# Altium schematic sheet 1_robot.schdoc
size 302 x 203 mm; Symbol: Altium_A4; Device: Altium_A4; Width: 1150; Height: 760; X Region Count: 6; Y Region Count: 4; Blade Width: 20; Region Start: 1; Title Block Position: 3; @Page No: 1; @Page Count: 1; @Schematic Name: robot; @Project Name: robot; @Board Name: robot; @Update Date: 2025-04-05; @Create Time: 22:42:32; @Update Time: 23:08:08; @Page Name: robot; @Create Date: 2025-04-01
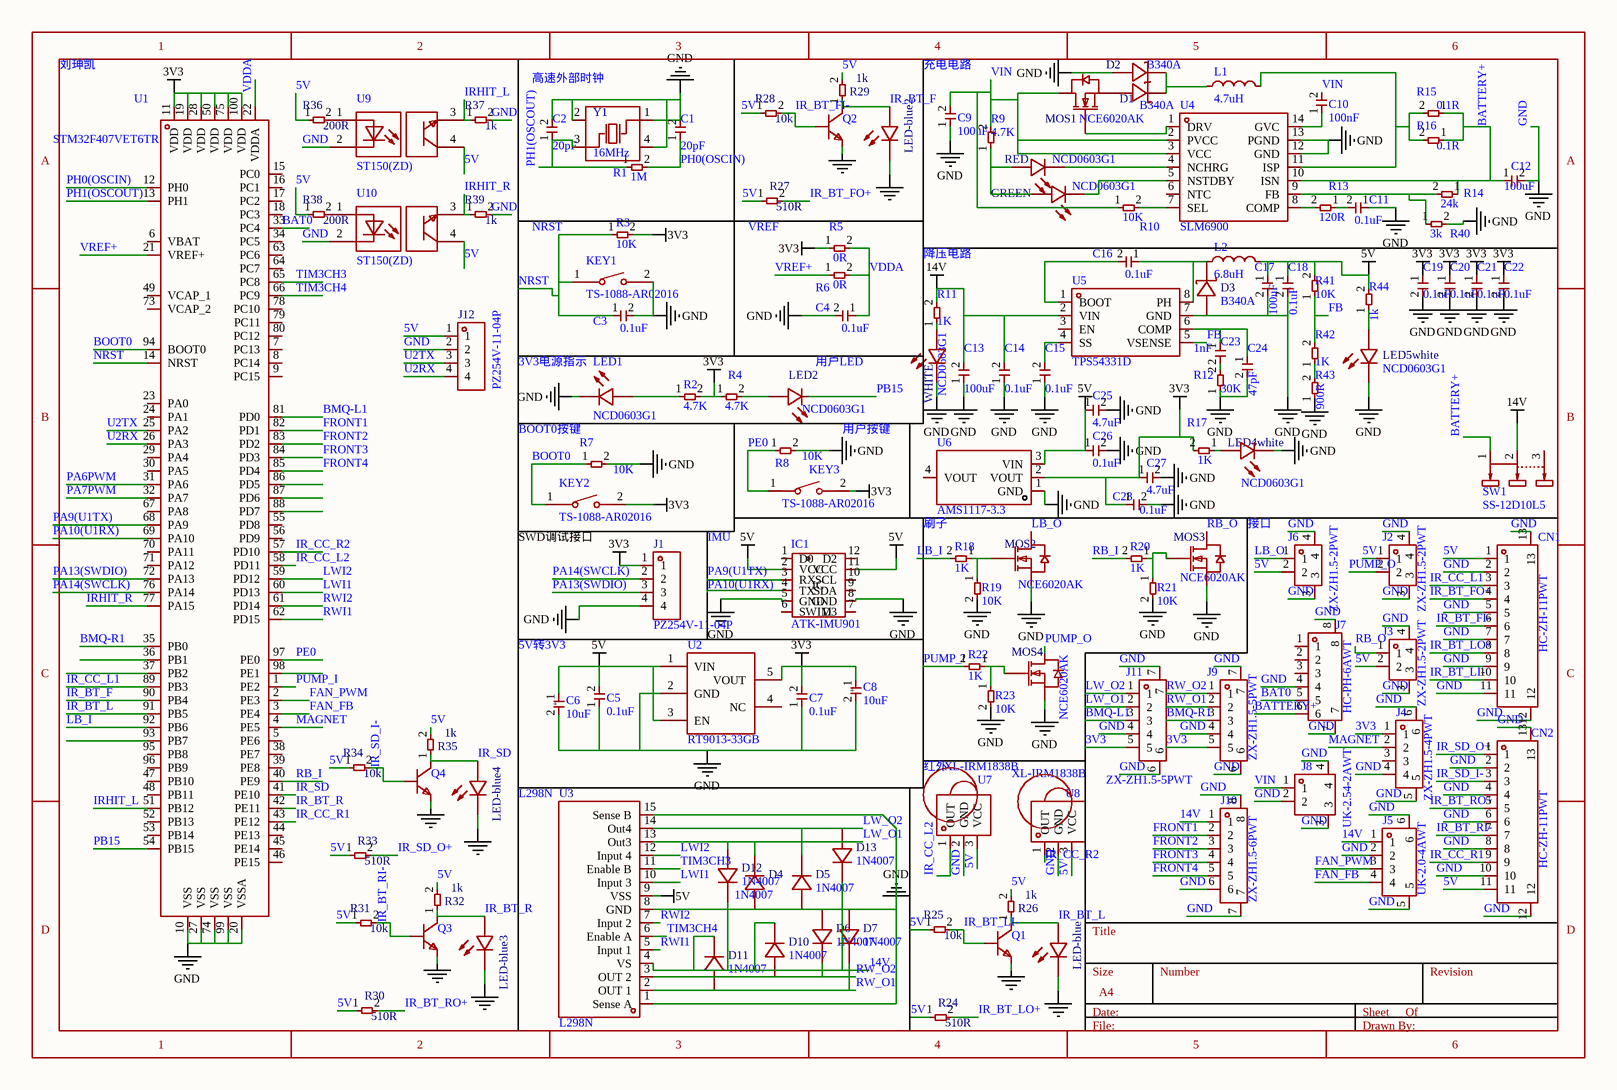
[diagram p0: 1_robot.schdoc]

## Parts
C1  20pF  [C0805]
C2  20pF  [C0805]
C3  0.1uF  [C0805]
C4  0.1uF  [C0805]
C5  0.1uF  [C0805]
C6  10uF  [c8050]
C7  0.1uF  [C0805]
C8  10uF  [c8050]
C9  100uF  [C0805]
C10  100nF  [C0805]
C11  0.1uF  [C0805]
C12  100uF  [C0805]
C13  100uF  [C0805]
C14  0.1uF  [C0805]
C15  0.1uF  [C0805]
C16  0.1uF  [C0805]
C17  100uF  [C0805]
C18  0.1uF  [C0805]
C19  0.1uF  [C0805]
C20  0.1uF  [C0805]
C21  0.1uF  [C0805]
C22  0.1uF  [C0805]
C23  1nF  [C0805]
C24  47pF  [C0805]
C25  4.7uF  [C0805]
C26  0.1uF  [C0805]
C27  4.7uF  [C0805]
C28  0.1uF  [C0805]
CN1  HC-ZH-11PWT  [CONN-SMD_11P-P1.50_HCTL_HC-ZH-11PWT]
CN2  HC-ZH-11PWT  [CONN-SMD_11P-P1.50_HCTL_HC-ZH-11PWT]
D1  B340A  [SMA_L4.3-W2.6-LS5.1-RD]
D2  B340A  [SMA_L4.3-W2.6-LS5.1-RD]
D3  B340A  [SMA_L4.3-W2.6-LS5.1-RD]
D4  1N4007  [SMA_L4.3-W2.5-LS5.0-RD]
D5  1N4007  [SMA_L4.3-W2.5-LS5.0-RD]
D6  1N4007  [SMA_L4.3-W2.5-LS5.0-RD]
D7  1N4007  [SMA_L4.3-W2.5-LS5.0-RD]
D10  1N4007  [SMA_L4.3-W2.5-LS5.0-RD]
D11  1N4007  [SMA_L4.3-W2.5-LS5.0-RD]
D12  1N4007  [SMA_L4.3-W2.5-LS5.0-RD]
D13  1N4007  [SMA_L4.3-W2.5-LS5.0-RD]
GREEN  NCD0603G1  [LED0603-RD_1]
IC1  ATK-IMU901  [COMM-SMD_12P-L16.0-W15.5-P2.54_ATK-IMU901]
J1  PZ254V-11-04P  [HDR-TH_4P-P2.54-V-M]
J2  ZX-ZH1.5-2PWT  [CONN-SMD_2P-P1.50_ZX-ZH1.5-2PWT]
J3  ZX-ZH1.5-2PWT  [CONN-SMD_2P-P1.50_ZX-ZH1.5-2PWT]
J4  ZX-ZH1.5-4PWT  [CONN-SMD_4P-P1.50_ZX-ZH1.5-4PWT]
J5  UK-2.0-4AWT  [CONN-SMD_4P-P2.00_USAKRO_UK-2.0-4AWT]
J6  ZX-ZH1.5-2PWT  [CONN-SMD_2P-P1.50_ZX-ZH1.5-2PWT]
J7  HC-PH-6AWT  [CONN-SMD_6P-P2.00_HCTL_HC-PH-6AWT]
J8  UK-2.54-2AWT  [CONN-SMD_2P-P2.54_USAKRO_UK-2.54-2AWT]
J9  ZX-ZH1.5-5PWT  [CONN-SMD_5P-P1.50_ZX-ZH1.5-5PWT]
J10  ZX-ZH1.5-6PWT  [CONN-SMD_6P-P1.50_ZX-ZH1.5-6PWT]
J11  ZX-ZH1.5-5PWT  [CONN-SMD_5P-P1.50_ZX-ZH1.5-5PWT]
J12  PZ254V-11-04P  [HDR-TH_4P-P2.54-V-M]
KEY1  TS-1088-AR02016  [SW-SMD_L3.9-W3.0-P4.45]
KEY2  TS-1088-AR02016  [SW-SMD_L3.9-W3.0-P4.45]
KEY3  TS-1088-AR02016  [SW-SMD_L3.9-W3.0-P4.45]
L1  4.7uH  [IND-SMD_L2.5-W2.0-VLS252012CX-150M]
L2  6.8uH  [IND-SMD_L2.5-W2.0-VLS252012CX-150M]
LED1  NCD0603G1  [LED0603-RD_1]
LED2  NCD0603G1  [LED0603-RD_1]
LED4white  NCD0603G1  [LED0603-RD_1]
LED5white  NCD0603G1  [LED0603-RD_1]
LED-blue  NCD0603G1  [LED0603-RD_1]  (value not drawn)
LED-blue2  NCD0603G1  [LED0603-RD_1]  (value not drawn)
LED-blue3  NCD0603G1  [LED0603-RD_1]  (value not drawn)
LED-blue4  NCD0603G1  [LED0603-RD_1]  (value not drawn)
MOS1  NCE6020AK  [TO-252-2_L6.6-W6.1-P4.57-LS10.1-TL-CW]
MOS2  NCE6020AK  [TO-252-2_L6.6-W6.1-P4.57-LS10.1-TL-CW]
MOS3  NCE6020AK  [TO-252-2_L6.6-W6.1-P4.57-LS10.1-TL-CW]
MOS4  NCE6020AK  [TO-252-2_L6.6-W6.1-P4.57-LS10.1-TL-CW]
Q1  S8050 J3Y(RANGE:200-350)  [SOT-23-3_L3.0-W1.7-P0.95-LS2.9-BR]  (value not drawn)
Q2  S8050 J3Y(RANGE:200-350)  [SOT-23-3_L3.0-W1.7-P0.95-LS2.9-BR]  (value not drawn)
Q3  S8050 J3Y(RANGE:200-350)  [SOT-23-3_L3.0-W1.7-P0.95-LS2.9-BR]  (value not drawn)
Q4  S8050 J3Y(RANGE:200-350)  [SOT-23-3_L3.0-W1.7-P0.95-LS2.9-BR]  (value not drawn)
R1  1M  [R0805]
R2  4.7K  [R0805]
R3  10K  [R0805]
R4  4.7K  [R0805]
R5  0R  [R0805]
R6  0R  [R0805]
R7  10K  [R0805]
R8  10K  [R0805]
R9  4.7K  [R0805]
R10  10K  [R0805]
R11  1K  [R0805]
R12  30K  [R0805]
R13  120R  [R0805]
R14  24k  [R0805]
R15  0.1R  [R0805]
R16  0.1R  [R0805]
R17  1K  [R0805]
R18  1K  [R0805]
R19  10K  [R0805]
R20  1K  [R0805]
R21  10K  [R0805]
R22  1K  [R0805]
R23  10K  [R0805]
R24  510R  [R0805]
R25  10k  [R0805]
R26  1k  [R0805]
R27  510R  [R0805]
R28  10k  [R0805]
R29  1k  [R0805]
R30  510R  [R0805]
R31  10k  [R0805]
R32  1k  [R0805]
R33  510R  [R0805]
R34  10k  [R0805]
R35  1k  [R0805]
R36  200R  [R0805]
R37  1k  [R0805]
R38  200R  [R0805]
R39  1k  [R0805]
R40  3k  [R0805]
R41  10K  [R0805]
R42  1K  [R0805]
R43  900R  [R0805]
R44  1k  [R0805]
RED  NCD0603G1  [LED0603-RD_1]
SW1  SS-12D10L5  [SW-TH_SS-12D10L5]
U1  STM32F407VET6TR  [LQFP-100_L14.0-W14.0-P0.50-LS16.0-BL-EP6.0]
U2  RT9013-33GB  [SOT-23-5_L3.0-W1.7-P0.95-LS2.8-BL]
U3  L298N  [MULTIWATT-15_L19.6-W5.0-P1.27-L]
U4  SLM6900  [TSSOP-14_L5.0-W4.4-P0.65-LS6.4-BL]
U5  TPS54331D  [SOIC-8_L4.9-W3.9-P1.27-LS6.0-BL]
U6  AMS1117-3.3  [SOT-223-3_L6.5-W3.4-P2.30-LS7.0-BR]
U7  XL-IRM1838B  [OPTO-TH_3P-L7.0-W5.6-P2.54-L]
U8  XL-IRM1838B  [OPTO-TH_3P-L7.0-W5.6-P2.54-L]
U9  ST150(ZD)  [OPTO-TH_L12.7-W5.8_ST150]
U10  ST150(ZD)  [OPTO-TH_L12.7-W5.8_ST150]
WHITE  NCD0603G1  [LED0603-RD_1]
Y1  16MHz  [OSC-SMD_4P-L3.2-W2.5-BL]

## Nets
3V3: C7.2 C8.1 C19.1 C20.1 C21.1 C22.1 C27.1 C28.1 J1.1 J4.1 J9.5 J11.5 KEY2.2 KEY3.2 R2.2 R3.2 R4.1 R5.1 R17.2 U1.11(VDD) U1.19(VDD) U1.28(VDD) U1.50(VDD) U1.75(VDD) U1.100(VDD) U2.5(VOUT) U6.2(VOUT)
5V: C5.2 C6.1 C17.1 C18.1 C25.1 C26.1 CN1.1 CN2.11 IC1.2(VCC) IC1.11(VCC) J2.1 J3.2 J6.2 J12.1 L2.2 R24.1 R25.1 R26.2 R27.1 R28.1 R29.2 R30.1 R31.1 R32.2 R33.1 R34.1 R35.2 R36.1 R38.1 R41.2 R44.2 U2.1(VIN) U2.3(EN) U3.9(VSS) U6.3(VIN) U7.3(VCC) U8.3(VCC) U9.4(COLLECTOR) U10.4(COLLECTOR)
14V: C13.2 C14.2 D10.1(K) D11.1(K) D12.1(K) D13.1(K) J5.1 J10.1 R11.2 SW1.2 U3.4(VS) U5.2(VIN)
GND: C1.2 C2.2 C3.2 C4.2 C5.1 C6.2 C7.1 C8.2 C9.1 C11.1 C12.2 C13.1 C14.1 C15.1 C17.2 C18.2 C19.2 C20.2 C21.2 C22.2 C24.2 C25.2 C26.2 C27.2 C28.2 CN1.2 CN1.5 CN1.7 CN1.9 CN1.11 CN1.12 CN1.13 CN2.2 CN2.4 CN2.6 CN2.8 CN2.10 CN2.12 CN2.13 D2.2(A) D3.2(A) D4.2(A) D5.2(A) D6.2(A) D7.2(A) IC1.5(GND) IC1.8(GND) J1.4 J2.3 J2.4 J3.3 J3.4 J4.4 J4.5 J4.6 J5.2 J5.5 J5.6 J6.3 J6.4 J7.4 J7.7 J7.8 J8.2 J8.3 J8.4 J9.4 J9.6 J9.7 J10.6 J10.7 J10.8 J11.4 J11.6 J11.7 J12.2 KEY1.2 LED1.1(K) LED4white.1(K) LED5white.1(K) LED-blue.1(K) LED-blue2.1(K) LED-blue3.1(K) LED-blue4.1(K) MOS2.3(S) MOS3.3(S) MOS4.3(S) Q1.2(E) Q2.2(E) Q3.2(E) Q4.2(E) R7.2 R8.2 R12.1 R19.2 R21.2 R23.2 R37.2 R39.2 R40.2 R43.1 U1.10(VSS) U1.20(VSSA) U1.27(VSS) U1.74(VSS) U1.99(VSS) U2.2(GND) U3.1(Sense_A) U3.8(GND) U3.15(Sense_B) U4.12(GND) U4.13(PGND) U5.7(GND) U6.1(GND) U7.2(GND) U8.2(GND) U9.2(CATHODE) U10.2(CATHODE) WHITE.1(K) Y1.1(OSC1) Y1.2(GND) Y1.4(GND)
BAT0: J7.5 U1.33(PC4)
BATTERY+: C12.1 J7.6 R14.1 R15.1 R16.1 SW1.1 U4.10(ISN)
BMQ-L1: J11.3 U1.81(PD0)
BMQ-R1: J9.3 U1.35(PB0)
BOOT0: KEY2.1 R7.1 U1.94(BOOT0)
FAN_FB: J5.4 U1.3(PE4)
FAN_PWM: J5.3 U1.2(PE3)
FB: R41.1 R42.2 U5.5(VSENSE)
FRONT1: J10.2 U1.82(PD1)
FRONT2: J10.3 U1.83(PD2)
FRONT3: J10.4 U1.84(PD3)
FRONT4: J10.5 U1.85(PD4)
IR_BT_F: LED-blue2.2(A) Q2.3(C) R29.1 U1.90(PB4)
IR_BT_FI-: CN1.6 Q2.1(B) R28.2
IR_BT_FO+: CN1.4 R27.2
IR_BT_L: LED-blue.2(A) Q1.3(C) R26.1 U1.91(PB5)
IR_BT_LI-: CN1.10 Q1.1(B) R25.2
IR_BT_LO+: CN1.8 R24.2
IR_BT_R: LED-blue3.2(A) Q3.3(C) R32.1 U1.42(PE11)
IR_BT_RI-: CN2.7 Q3.1(B) R31.2
IR_BT_RO+: CN2.5 R30.2
IR_CC_L1: CN1.3 U1.89(PB3)
IR_CC_L2: U1.58(PD11) U7.1(OUT)
IR_CC_R1: CN2.9 U1.43(PE12)
IR_CC_R2: U1.57(PD10) U8.1(OUT)
IR_SD: LED-blue4.2(A) Q4.3(C) R35.1 U1.41(PE10)
IR_SD_I-: CN2.3 Q4.1(B) R34.2
IR_SD_O+: CN2.1 R33.2
IRHIT_L: R37.1 U1.51(PB12) U9.3(EMITTER)
IRHIT_R: R39.1 U1.77(PA15) U10.3(EMITTER)
LB_I: R18.2 U1.92(PB6)
LB_O: J6.1 MOS2.2(D)
LW_O1: D4.1(K) D12.2(A) J11.2 U3.13(Out3)
LW_O2: D5.1(K) D13.2(A) J11.1 U3.14(Out4)
LWI1: U1.60(PD13) U3.10(Input_3)
LWI2: U1.59(PD12) U3.12(Input_4)
MAGNET: J4.2 U1.4(PE5)
NRST: C3.1 KEY1.1 R3.1 U1.14(NRST)
PA6PWM: U1.31(PA6)
PA7PWM: U1.32(PA7)
PA9(U1TX): IC1.3(RX) U1.68(PA9)
PA10(U1RX): IC1.4(TX) U1.69(PA10)
PA13(SWDIO): J1.3 U1.72(PA13)
PA14(SWCLK): J1.2 U1.76(PA14)
PB15: LED2.1(K) U1.54(PB15)
PE0: KEY3.1 R8.1 U1.97(PE0)
PH0(OSCIN): C1.1 R1.2 U1.12(PH0)
PH1(OSCOUT): C2.1 R1.1 U1.13(PH1) Y1.3(OSC2)
PUMP_I: R22.2 U1.1(PE2)
PUMP_O: J2.2 MOS4.2(D)
RB_I: R20.2 U1.40(PE9)
RB_O: J3.1 MOS3.2(D)
RW_O1: D7.1(K) D11.2(A) J9.2 U3.2(OUT_1)
RW_O2: D6.1(K) D10.2(A) J9.1 U3.3(OUT_2)
RWI1: U1.62(PD15) U3.5(Input_1)
RWI2: U1.61(PD14) U3.7(Input_2)
TIM3CH3: U1.65(PC8) U3.11(Enable_B)
TIM3CH4: U1.66(PC9) U3.6(Enable_A)
U2RX: J12.4 U1.26(PA3)
U2TX: J12.3 U1.25(PA2)
VDDA: C4.1 R5.2 R6.2 U1.22(VDDA)
VIN: C9.2 C10.2 J8.1 MOS1.2(D) R9.2 R10.1 U4.2(PVCC) U4.3(VCC)
VREF+: R6.1 U1.21(VREF+)
NetC10_1: C10.1 U4.14(GVC)
NetC11_2: C11.2 R13.1
NetC15_2: C15.2 U5.4(SS)
NetC16_1: C16.1 D3.1(K) L2.1 U5.8(PH)
NetC16_2: C16.2 U5.1(BOOT)
NetC23_1: C23.1 C24.1 U5.6(COMP)
NetC23_2: C23.2 R12.2
NetD1_1: D1.1(K) D2.1(K) L1.1
NetD1_2: D1.2(A) MOS1.3(S)
NetGREEN_1: GREEN.1(K) U4.5(NSTDBY)
NetGREEN_2: GREEN.2(A) R9.1 RED.2(A)
NetL1_2: L1.2 R15.2 R16.2 U4.11(ISP)
NetLED1_2: LED1.2(A) R2.1
NetLED2_2: LED2.2(A) R4.2
NetLED4white_2: LED4white.2(A) R17.1
NetLED5white_2: LED5white.2(A) R44.1
NetMOS1_1: MOS1.1(G) U4.1(DRV)
NetMOS2_1: MOS2.1(G) R18.1 R19.1
NetMOS3_1: MOS3.1(G) R20.1 R21.1
NetMOS4_1: MOS4.1(G) R22.1 R23.1
NetR10_2: R10.2 U4.7(SEL)
NetR11_1: R11.1 WHITE.2(A)
NetR13_2: R13.2 U4.8(COMP)
NetR14_2: R14.2 R40.1 U4.9(FB)
NetR36_2: R36.2 U9.1(ANODE)
NetR38_2: R38.2 U10.1(ANODE)
NetR42_1: R42.1 R43.2
NetRED_1: RED.1(K) U4.4(NCHRG)

Not connected (* = marked no-connect by the designer): IC1 1(D0) 6(SWIM) 7(D3) 9(SDA) 10(SCL) 12(D2); J4 3; J7 1 2 3; SW1 3; U1 5(PE6) 6(VBAT) 7(PC13) 8(PC14) 9(PC15) 15(PC0) 16(PC1) 17(PC2) 18(PC3) 23(PA0) 24(PA1) 29(PA4) 30(PA5) 34(PC5) 36(PB1) 37(PB2) 38(PE7) 39(PE8) 44(PE13) 45(PE14) 46(PE15) 47(PB10) 48(PB11) 49(VCAP_1) 52(PB13) 53(PB14) 55(PD8) 56(PD9) 63(PC6) 64(PC7) 67(PA8) 70(PA11) 71(PA12) 73(VCAP_2) 78(PC10) 79(PC11) 80(PC12) 86(PD5) 87(PD6) 88(PD7) 93(PB7) 95(PB8) 96(PB9) 98(PE1); U2 4(NC); U4 6(NTC); U5 3(EN); U6 4(VOUT)

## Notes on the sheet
- 刘珅凯
- 高速外部时钟
- 充电电路
- NRST
- (near R27) VREF
- (near R11) 降压电路
- 3V3电源指示
- 用户LED
- BOOT0按键
- 用户按键
- (near KEY2) SWD调试接口
- IMU
- 刷子
- 接口
- 5V转3V3
- 红外
- (near LED-blue4) L298N

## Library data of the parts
C1 C2 = 20pF: Symbol: Capacitance; Add into BOM: yes
C3-C5 C7 C11 C14-C16 C18-C22 C26 C28 = 0.1uF: Symbol: Capacitance; Add into BOM: yes
C6 C8 = 10uF: Symbol: Capacitance+; Add into BOM: yes; Origin Footprint: C_8MM
C9 C12 C13 C17 = 100uF: Symbol: Capacitance; Add into BOM: yes
C10 = 100nF: Symbol: Capacitance; Add into BOM: yes
C23 = 1nF: Symbol: Capacitance; Add into BOM: yes
C24 = 47pF: Symbol: Capacitance; Add into BOM: yes
C25 C27 = 4.7uF: Symbol: Capacitance; Add into BOM: yes
CN1 CN2 = HC-ZH-11PWT: Manufacturer: HCTL(华灿天禄); Symbol: HC-ZH-11PWTKK; Add into BOM: yes; Pins Structure: 1x11P; Pitch: 1.5mm; Reference Series: ZH; Number of PINs Per Row: 11; Current Rating (Max): 1A; Rated Voltage (Max): 100V; Plastic Material: PA46; Flame Retardant Rating: UL94V-0; Supplementary Features: 辅助焊脚; Z-Height of the Board: 3.8mm; X-Length of Bottom Edge on Board (Spacing Line): 19.5mm; Y-Width of Bottom Edge on Board: 6.5mm
D1-D3 = B340A: Manufacturer: MDD(辰达半导体); Add into BOM: yes; Diode Configuration: 独立式; Forward Voltage (Vf@If): 550mV@3A; Reverse Voltage (Vr): 40V; Rectified Current: 3A; Reverse Leakage Current (Ir): 500uA@40V
D4-D7 D10-D13 = 1N4007_C727081: Manufacturer: TWGMC(台湾迪嘉); Add into BOM: yes; Diode Configuration: 独立式; Forward Voltage (Vf@If): 1.1V@1A; Reverse Voltage (Vr): 1kV; Rectified Current: 1A; Reverse Leakage Current (Ir): 5uA
GREEN LED1 LED2 LED4white LED5white LED-blue LED-blue2-LED-blue4 RED WHITE = NCD0603G1: Manufacturer: 国星光电; Symbol: FC-D1608UGK-520D10; Add into BOM: yes; Illumination Color: 翠绿色; Voltage - Forward(Vf): 2.6V~3.6V; Power(Watts): 72mW; Forward Current: 20mA; Wavelength - Dominant: 515nm~530nm; Luminous Intensity: 330mcd~900mcd; Viewing Angle: 130°
IC1 = Sensor_IMU: Origin Footprint 2: imu; Add into BOM: yes; Origin Footprint 1: SENSOE_IMU
J1 J12 = PZ254V-11-04P: Manufacturer: XFCN(兴飞); Symbol: PZ254V-11-04P_C2691448; Add into BOM: yes; Pin Structure: 1x4P; Pitch: 2.54mm; Circluar Pins/Square Pins: 方针; Current Rating (Max): 3A; Voltage Rating (Max): 250V
J2 J3 J6 = ZX-ZH1.5-2PWT: Manufacturer: Megastar(兆星); Add into BOM: yes; Pins Structure: 1x2P; Pitch: 1.5mm; Reference Series: ZH; Number of PINs Per Row: 2; Rated Current: 1A; Rated Voltage (Max): 250V; Plastic Material: LCP; Supplementary Features: 辅助焊脚; Z-Height of the Board: 3.8mm; X-Length of Bottom Edge on Board (Spacing Line): 6mm; Y-Width of Bottom Edge on Board: 6.5mm
J4 = ZX-ZH1.5-4PWT: Manufacturer: Megastar(兆星); Add into BOM: yes; Pins Structure: 1x4P; Pitch: 1.5mm; Reference Series: ZH; Number of PINs Per Row: 4; Rated Current: 1A; Rated Voltage (Max): 250V; Plastic Material: LCP; Supplementary Features: 辅助焊脚; Z-Height of the Board: 3.8mm; X-Length of Bottom Edge on Board (Spacing Line): 9mm; Y-Width of Bottom Edge on Board: 6.5mm
J5 = UK-2.0-4AWT: Manufacturer: USAKRO(美韩); Add into BOM: yes; Pins Structure: 1x4P; Pitch: 2mm; Number of PINs Per Row: 4; Current Rating (Max): 2A
J7 = HC-PH-6AWT: Manufacturer: HCTL(华灿天禄); Add into BOM: yes; Pins Structure: 1x6P; Pitch: 2mm; Reference Series: PH; Number of PINs Per Row: 6; Current Rating (Max): 2A; Rated Voltage (Max): 250V; Flame Retardant Rating: UL94V-0; Z-Height of the Board: 5.5mm; X-Length of Bottom Edge on Board (Spacing Line): 16mm; Y-Width of Bottom Edge on Board: 8.65mm
J8 = UK-2.54-2AWT: Manufacturer: USAKRO(美韩); Add into BOM: yes; Pins Structure: 1x2P; Pitch: 2.54mm; Reference Series: XH; Number of PINs Per Row: 2; Current Rating (Max): 3A
J9 J11 = ZX-ZH1.5-5PWT: Manufacturer: Megastar(兆星); Add into BOM: yes; Pins Structure: 1x5P; Pitch: 1.5mm; Reference Series: ZH; Number of PINs Per Row: 5; Rated Current: 1A; Rated Voltage (Max): 250V; Plastic Material: LCP; Supplementary Features: 辅助焊脚; Z-Height of the Board: 3.8mm; X-Length of Bottom Edge on Board (Spacing Line): 10.5mm; Y-Width of Bottom Edge on Board: 6.5mm
J10 = ZX-ZH1.5-6PWT: Manufacturer: Megastar(兆星); Add into BOM: yes; Pins Structure: 1x6P; Pitch: 1.5mm; Reference Series: ZH; Number of PINs Per Row: 6; Rated Current: 1A; Rated Voltage (Max): 250V; Plastic Material: LCP; Supplementary Features: 辅助焊脚; Z-Height of the Board: 3.8mm; X-Length of Bottom Edge on Board (Spacing Line): 12mm; Y-Width of Bottom Edge on Board: 6.5mm
KEY1-KEY3 = TS-1088-AR02016: Manufacturer: XUNPU(讯普); Add into BOM: yes; Circuit: 单刀单掷; Actuator Style: 圆形按钮; Operating Force: 160gf; Switch Length: 4mm; Switch Width: 3mm; Switch Height: 2mm; Strike Gundam: 不带; Contact Current: 50mA; Voltage Rating (DC): 12V; Insulation Resistance: 100MΩ; Actuator/Cap Color: 黑色; Pin Style: SMD接片; Mechanical Life: 10万次
L1 L2 = FTC252010S4R7MBCA: Manufacturer: cjiang(长江微电); Add into BOM: yes; Tolerance: ±20%; Rated Current: 2A; Saturation Current (Isat): 2.6A; DC Resistance (DCR): 160mΩ; Type: 一体成型电感
MOS1-MOS4 = NCE6020AK: Manufacturer: NCE(无锡新洁能); Add into BOM: yes; Drain to Source Voltage: 60V; Current - Continuous Drain(Id): 20A; RDS(on): 35mΩ@10V,24A; Pd - Power Dissipation: 45W; Gate Threshold Voltage (Vgs(th)@Id): 2.5V; Gate Charge(Qg): 25nC@10V; Input Capacitance(Ciss@Vds): 973.2pF@30V; Reverse Transfer Capacitance (Crss@Vds): 58.8pF@30V
Q1-Q4 = S8050 J3Y(RANGE:200-350): Manufacturer: CJ(江苏长电/长晶); Symbol: S8050_C2146; Add into BOM: yes; type: NPN; Current - Collector(Ic): 500mA; Collector - Emitter Voltage VCEO: 25V; Pd - Power Dissipation: 300mW; DC Current Gain: 200@500mA,1V; Transition frequency(fT): 150MHz; Current - Collector Cutoff: 100nA; Vce Saturation(VCE(sat)): 600mV
R1 = 1M: Symbol: Resistance; Add into BOM: yes
R2 R4 R9 = 4.7K: Symbol: Resistance; Add into BOM: yes
R3 R7 R8 R10 R19 R21 R23-R39 R41 = 10K: Symbol: Resistance; Add into BOM: yes
R5 R6 = 0R: Symbol: Resistance; Add into BOM: yes
R11 R17 R18 R20 R22 R42 R44 = 1K: Symbol: Resistance; Add into BOM: yes
R12 = 30K: Symbol: Resistance; Add into BOM: yes
R13 = 120R: Symbol: Resistance; Add into BOM: yes
R14 = 24k: Symbol: Resistance; Add into BOM: yes
R15 R16 = 0.1R: Symbol: Resistance; Add into BOM: yes
R40 = 3k: Symbol: Resistance; Add into BOM: yes
R43 = 900R: Symbol: Resistance; Add into BOM: yes
SW1 = SS-12D10L5: Manufacturer: XKB Connectivity(中国星坤); Add into BOM: yes; Circuit: 单刀双掷; Actuator Style: 矩形柱状; Pin Style: PC引脚; Switch Length: 13mm; Switch Width: 6.8mm; Switch Height: 6.4mm; Actuator Color: 黑色; Current Rating (DC): 3A; Voltage Rating (DC): 125V; Mechanical Life: 1万次
U1 = STM32F407VET6TR: Manufacturer: ST(意法半导体); Symbol: STM32F407VET6TR_1; Add into BOM: yes; CPU Core: ARM-M4; CPU Maximum Speed: 168MHz; Number of I/O: 82; ADC (Bit): 12bit; Low Voltage Detection Threshold: 1.8V~3.6V; Origin Footprint 2: IND-TH_4P-L19.0-W13.0-P8.00-D0.7-S7.00
U2 = RT9013-33GB: Manufacturer: RICHTEK(立锜); Add into BOM: yes; Output Type: 固定; Maximum Input Voltage: 5.5V; Output Voltage: 3.3V; Output Current: 500mA; Power Supply Rejection Ratio (PSRR): 50dB@(10kHz); Dropout Voltage: 400mV@(500mA); standby current: 50uA; Output Polarity: 正极; Number of Outputs: 1
U3 = L298N_C19922: Manufacturer: ST(意法半导体); Add into BOM: yes
U4 = SLM6900: Manufacturer: 无锡松朗微; Add into BOM: yes; The Chip Type: 降压充电芯片; Supply Voltage: 8V~30V; Maximum Charge Current: 6A; Charging Saturation Voltage: 25.2V; Type of Battery: 锂离子/聚合物; Number of Cells: 2~6
U5 = TPS54331D: Manufacturer: TI(德州仪器); Add into BOM: yes; Function: 降压型; Output Type: 可调; Input Voltage: 3.5V~28V; Output Current: 3A; Switching Frequency: 570kHz; Synchronous Rectification: 否; Number of Outputs: 1; Topology: 降压式; Quiescent Current (Iq): 1uA; Switch tube (built-in/external): 内置
U6 = AMS1117-3.3: Manufacturer: AMS; Symbol: AMS1117-3.3_C6186; Add into BOM: yes; Output Type: 固定; Output Voltage: 3.3V; Output Current: 1A; Power Supply Rejection Ratio (PSRR): 72dB@(120Hz); Voltage Dropout: 1.3V@(800mA); Output Configuration: 正极; Number of Outputs: 1
U7 U8 = XL-IRM1838B: Manufacturer: XINGLIGHT(成兴光); Add into BOM: yes
U9 U10 = ST150(ZD): Manufacturer: Chau Light(洲光源); Add into BOM: yes; Slot Width: 5mm; Forward Voltage (Typ): 1.2V; C-E Saturation Voltage: 400mV; Collector Current (Max): 500uA; Dark Current: 100nA; Peak Wavelength: 940nm; Rise Time: 15us
Y1 = X322516MLB4SI: Manufacturer: YXC(扬兴晶振); Add into BOM: yes; Normal temperature Frequency Tolerance: ±10ppm; Load Capacitance: 9pF; Frequency Stability: ±20ppm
